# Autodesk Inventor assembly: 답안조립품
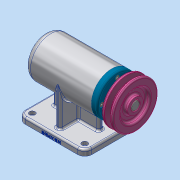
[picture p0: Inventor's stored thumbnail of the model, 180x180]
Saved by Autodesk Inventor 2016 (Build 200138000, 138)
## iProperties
Created: 2020-10
Part Number: 답안조립품
Document SubType Name: Assembly
Designer: user
Author: user
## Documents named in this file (12)
- C:\Users\user\OneDrive\바탕 화면\701004V1012\답안조립품.iam
- C:\Users\user\OneDrive\바탕 화면\701004V1012\본체.ipt
- C:\Users\user\OneDrive\바탕 화면\701004V1012\V벨트풀리.ipt
- C:\Users\user\OneDrive\바탕 화면\701004V1012\멈춤나사 M3.ipt
- C:\Users\user\OneDrive\바탕 화면\701004V1012\베어링 6004.ipt
- C:\Users\user\OneDrive\바탕 화면\701004V1012\베어링 51202.ipt
- C:\Users\user\OneDrive\바탕 화면\701004V1012\볼트 M4.ipt
- C:\Users\user\OneDrive\바탕 화면\701004V1012\어댑터슬리브.ipt
- C:\Users\user\OneDrive\바탕 화면\701004V1012\오일 실.ipt
- C:\Users\user\OneDrive\바탕 화면\701004V1012\축.ipt
- C:\Users\user\OneDrive\바탕 화면\701004V1012\커버.ipt
- C:\Users\user\OneDrive\바탕 화면\701004V1012\키 5 x 5 x 16.ipt
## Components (1 placed, 1 different names)
1. V벨트풀리:1
